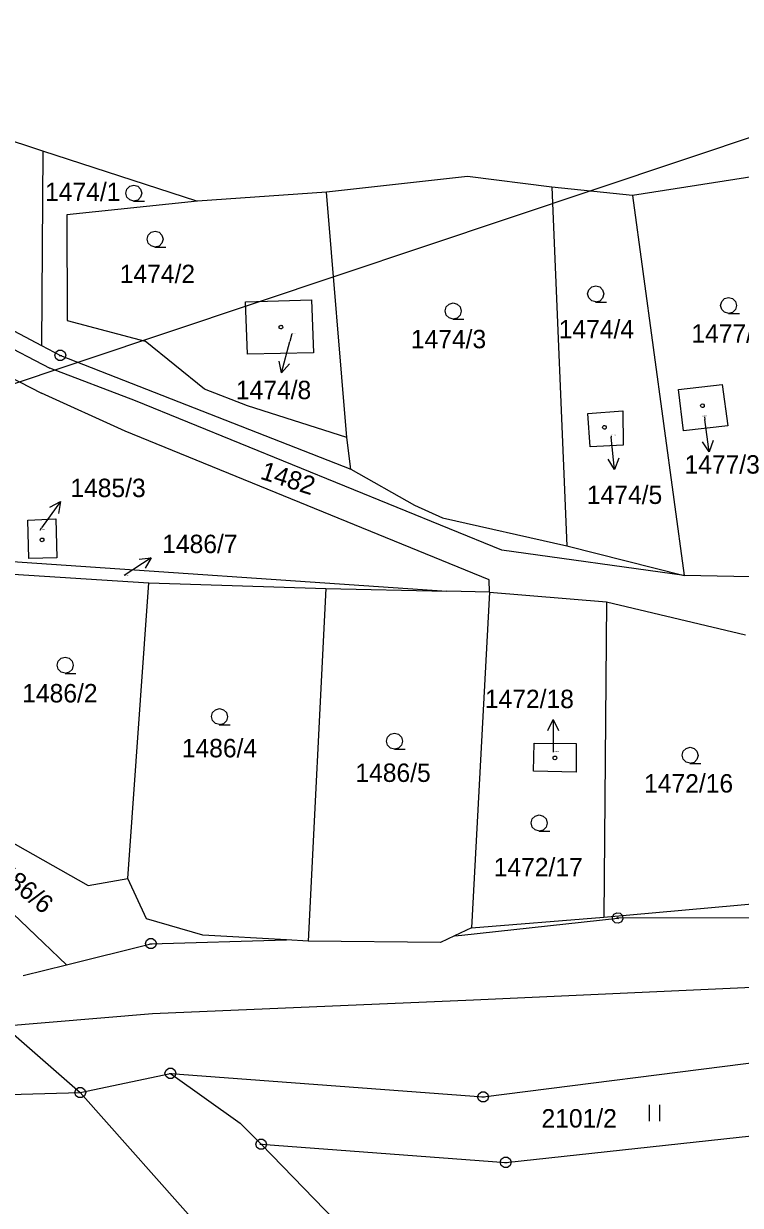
# Model space of a CAD drawing. Extents: x -806774 to -803680, y -1151731 to -1150053.
# Drawn here: x -805263 to -805196.8, y -1150678 to -1150569 of the extents above; entities that cross this region are included whole.
import ezdxf

# ---------------------------------------------------------------- set-up
doc = ezdxf.new("R2010")
doc.units = 0
for name, color, linetype in [('1', 7, 'Continuous'), ('12', 7, 'Continuous'), ('2', 7, 'Continuous'), ('3', 7, 'Continuous'), ('5', 7, 'Continuous'), ('6', 7, 'Continuous'), ('7', 7, 'Continuous'), ('8', 7, 'Continuous')]:
    doc.layers.add(name, color=color, linetype=linetype)

msp = doc.modelspace()

# ---------------------------------------------------------------- linework, layer by layer
at = {"layer": '1'}
for p, q in [((-805298.61, -1150579.03), (-805261.34, -1150598.68)), ((-805261.24, -1150580.73), (-805266.74, -1150578.94)), ((-805261.24, -1150580.73), (-805261.34, -1150598.68)), ((-805247.01, -1150585.35), (-805261.24, -1150580.73)), ((-805298.18, -1150581.32), (-805260.57, -1150600.77)), ((-805222.04, -1150583.09), (-805235.05, -1150584.53)), ((-805214.25, -1150584.07), (-805222.04, -1150583.09)), ((-805194.37, -1150582.88), (-805206.79, -1150584.83)), ((-805235.05, -1150584.53), (-805246.94, -1150585.36)), ((-805233.16, -1150607.18), (-805235.05, -1150584.53)), ((-805206.79, -1150584.83), (-805214.25, -1150584.07)), ((-805214.25, -1150584.07), (-805212.85, -1150617.17)), ((-805246.96, -1150585.36), (-805259.01, -1150586.6)), ((-805246.96, -1150585.36), (-805247.01, -1150585.35)), ((-805246.94, -1150585.36), (-805246.96, -1150585.36)), ((-805206.79, -1150584.83), (-805202.04, -1150619.89)), ((-805259.01, -1150586.6), (-805258.98, -1150596.36)), ((-805242.53, -1150594.64), (-805236.43, -1150594.46)), ((-805242.35, -1150599.49), (-805242.53, -1150594.64)), ((-805236.43, -1150594.46), (-805236.25, -1150599.34)), ((-805258.98, -1150596.36), (-805251.77, -1150598.28)), ((-805261.34, -1150598.68), (-805259.61, -1150599.59)), ((-805246.31, -1150602.71), (-805251.77, -1150598.28)), ((-805268.44, -1150599.44), (-805261.36, -1150603.09)), ((-805259.61, -1150599.59), (-805232.81, -1150610.08)), ((-805236.25, -1150599.34), (-805242.35, -1150599.49)), ((-805252.68, -1150603.77), (-805260.57, -1150600.77)), ((-805253.62, -1150606.59), (-805261.36, -1150603.09)), ((-805242.34, -1150604.24), (-805246.31, -1150602.71)), ((-805202.55, -1150602.73), (-805198.52, -1150602.28)), ((-805202.1, -1150606.56), (-805202.55, -1150602.73)), ((-805198.52, -1150602.28), (-805198.01, -1150606.08)), ((-805218.86, -1150617.58), (-805252.68, -1150603.77)), ((-805233.16, -1150607.18), (-805242.34, -1150604.24)), ((-805210.92, -1150604.95), (-805207.69, -1150604.71)), ((-805210.7, -1150608.02), (-805210.92, -1150604.95)), ((-805207.69, -1150604.71), (-805207.65, -1150607.87)), ((-805198.01, -1150606.08), (-805202.1, -1150606.56)), ((-805220.03, -1150620.31), (-805253.62, -1150606.59)), ((-805232.81, -1150610.08), (-805233.16, -1150607.18)), ((-805207.65, -1150607.87), (-805210.7, -1150608.02)), ((-805232.81, -1150610.08), (-805226.92, -1150613.4)), ((-805226.92, -1150613.4), (-805224.33, -1150614.59)), ((-805262.61, -1150614.81), (-805260.03, -1150614.67)), ((-805262.51, -1150618.33), (-805262.61, -1150614.81)), ((-805260.03, -1150614.67), (-805259.94, -1150618.26)), ((-805224.33, -1150614.59), (-805212.85, -1150617.17)), ((-805212.85, -1150617.17), (-805202.04, -1150619.89)), ((-805272.94, -1150618.01), (-805223.94, -1150621.35)), ((-805259.94, -1150618.26), (-805262.51, -1150618.33)), ((-805202.04, -1150619.89), (-805218.86, -1150617.58)), ((-805265.57, -1150619.68), (-805251.46, -1150620.59)), ((-805220.01, -1150621.44), (-805220.03, -1150620.31)), ((-805188.96, -1150620.19), (-805202.04, -1150619.89)), ((-805253.39, -1150647.87), (-805251.46, -1150620.59)), ((-805251.46, -1150620.59), (-805235.12, -1150621.11)), ((-805235.12, -1150621.11), (-805236.73, -1150653.66)), ((-805235.12, -1150621.11), (-805223.94, -1150621.35)), ((-805220.01, -1150621.44), (-805223.94, -1150621.35)), ((-805220.01, -1150621.44), (-805221.67, -1150652.43)), ((-805220.01, -1150621.44), (-805209.21, -1150622.35)), ((-805209.21, -1150622.35), (-805209.44, -1150651.45)), ((-805209.21, -1150622.35), (-805196.37, -1150625.39)), ((-805215.94, -1150637.96), (-805215.89, -1150635.38)), ((-805215.89, -1150635.38), (-805212, -1150635.4)), ((-805212, -1150635.4), (-805212, -1150638.05)), ((-805278.6, -1150637.23), (-805259.03, -1150655.84)), ((-805212, -1150638.05), (-805215.94, -1150637.96)), ((-805270.38, -1150640.96), (-805257.03, -1150648.53)), ((-805257.03, -1150648.53), (-805253.39, -1150647.87)), ((-805251.65, -1150651.59), (-805253.39, -1150647.87)), ((-805209.44, -1150651.45), (-805194.7, -1150650.11)), ((-805246.46, -1150653.1), (-805251.65, -1150651.59)), ((-805222.55, -1150653.1), (-805208.17, -1150651.53)), ((-805221.67, -1150652.43), (-805209.44, -1150651.45)), ((-805178.93, -1150651.45), (-805208.17, -1150651.53)), ((-805238.75, -1150653.54), (-805246.46, -1150653.1)), ((-805223.22, -1150653.17), (-805224.51, -1150653.79)), ((-805221.67, -1150652.43), (-805223.22, -1150653.17)), ((-805223.22, -1150653.17), (-805222.55, -1150653.1)), ((-805259.03, -1150655.84), (-805251.25, -1150653.89)), ((-805251.25, -1150653.89), (-805238.75, -1150653.54)), ((-805236.73, -1150653.66), (-805238.75, -1150653.54)), ((-805224.51, -1150653.79), (-805236.73, -1150653.66)), ((-805263.04, -1150656.84), (-805259.03, -1150655.84)), ((-805268.53, -1150658.22), (-805257.77, -1150667.64)), ((-805220.59, -1150668.04), (-805193.03, -1150664.54)), ((-805257.77, -1150667.64), (-805249.45, -1150665.86)), ((-805249.45, -1150665.86), (-805220.59, -1150668.04)), ((-805249.45, -1150665.86), (-805243, -1150670.46)), ((-805267.02, -1150667.87), (-805257.77, -1150667.64)), ((-805257.77, -1150667.64), (-805232.77, -1150695.74)), ((-805243, -1150670.46), (-805241.07, -1150672.41)), ((-805218.5, -1150674.08), (-805189.9, -1150671)), ((-805241.07, -1150672.41), (-805218.5, -1150674.08)), ((-805241.07, -1150672.41), (-805221.06, -1150693))]:
    msp.add_line(p, q, dxfattribs=at)
at = {"layer": '12'}
for p, q in [((-805242.53, -1150594.64), (-805236.43, -1150594.46)), ((-805242.35, -1150599.49), (-805242.53, -1150594.64)), ((-805236.43, -1150594.46), (-805236.25, -1150599.34)), ((-805236.25, -1150599.34), (-805242.35, -1150599.49)), ((-805202.55, -1150602.73), (-805198.52, -1150602.28)), ((-805202.1, -1150606.56), (-805202.55, -1150602.73)), ((-805198.52, -1150602.28), (-805198.01, -1150606.08)), ((-805210.92, -1150604.95), (-805207.69, -1150604.71)), ((-805210.7, -1150608.02), (-805210.92, -1150604.95)), ((-805207.69, -1150604.71), (-805207.65, -1150607.87)), ((-805198.01, -1150606.08), (-805202.1, -1150606.56)), ((-805207.65, -1150607.87), (-805210.7, -1150608.02)), ((-805262.61, -1150614.81), (-805260.03, -1150614.67)), ((-805262.51, -1150618.33), (-805262.61, -1150614.81)), ((-805260.03, -1150614.67), (-805259.94, -1150618.26)), ((-805259.94, -1150618.26), (-805262.51, -1150618.33)), ((-805215.94, -1150637.96), (-805215.89, -1150635.38)), ((-805215.89, -1150635.38), (-805212, -1150635.4)), ((-805212, -1150635.4), (-805212, -1150638.05)), ((-805212, -1150638.05), (-805215.94, -1150637.96))]:
    msp.add_line(p, q, dxfattribs=at)
at = {"layer": '3'}
for p, q in [((-805205.27, -1150668.77), (-805205.27, -1150670.27)), ((-805204.27, -1150670.27), (-805204.27, -1150668.77))]:
    msp.add_line(p, q, dxfattribs=at)
for points in [[(-805252.83, -1150585.34), (-805253.21, -1150585.24), (-805253.48, -1150584.97), (-805253.58, -1150584.6), (-805253.48, -1150584.23), (-805253.21, -1150583.96), (-805252.84, -1150583.86), (-805252.47, -1150583.96), (-805252.2, -1150584.23), (-805252.1, -1150584.61), (-805252.2, -1150584.99), (-805252.47, -1150585.26), (-805252.85, -1150585.36), (-805251.85, -1150585.36)], [(-805250.86, -1150589.59), (-805251.24, -1150589.49), (-805251.51, -1150589.22), (-805251.61, -1150588.85), (-805251.51, -1150588.48), (-805251.24, -1150588.21), (-805250.87, -1150588.11), (-805250.5, -1150588.21), (-805250.23, -1150588.48), (-805250.13, -1150588.86), (-805250.23, -1150589.24), (-805250.5, -1150589.51), (-805250.88, -1150589.61), (-805249.88, -1150589.61)], [(-805210.19, -1150594.65), (-805210.57, -1150594.55), (-805210.84, -1150594.28), (-805210.94, -1150593.91), (-805210.84, -1150593.54), (-805210.57, -1150593.27), (-805210.2, -1150593.17), (-805209.83, -1150593.27), (-805209.56, -1150593.54), (-805209.46, -1150593.92), (-805209.56, -1150594.3), (-805209.83, -1150594.57), (-805210.21, -1150594.67), (-805209.21, -1150594.67)], [(-805197.92, -1150595.71), (-805198.3, -1150595.61), (-805198.57, -1150595.34), (-805198.67, -1150594.97), (-805198.57, -1150594.6), (-805198.3, -1150594.33), (-805197.93, -1150594.23), (-805197.56, -1150594.33), (-805197.29, -1150594.6), (-805197.19, -1150594.98), (-805197.29, -1150595.36), (-805197.56, -1150595.63), (-805197.94, -1150595.73), (-805196.94, -1150595.73)], [(-805223.34, -1150596.23), (-805223.72, -1150596.13), (-805223.99, -1150595.86), (-805224.09, -1150595.49), (-805223.99, -1150595.12), (-805223.72, -1150594.85), (-805223.35, -1150594.75), (-805222.98, -1150594.85), (-805222.71, -1150595.12), (-805222.61, -1150595.5), (-805222.71, -1150595.88), (-805222.98, -1150596.15), (-805223.36, -1150596.25), (-805222.36, -1150596.25)], [(-805259.16, -1150628.92), (-805259.54, -1150628.82), (-805259.81, -1150628.55), (-805259.91, -1150628.18), (-805259.81, -1150627.81), (-805259.54, -1150627.54), (-805259.17, -1150627.44), (-805258.8, -1150627.54), (-805258.53, -1150627.81), (-805258.43, -1150628.19), (-805258.53, -1150628.57), (-805258.8, -1150628.84), (-805259.18, -1150628.94), (-805258.18, -1150628.94)], [(-805244.92, -1150633.67), (-805245.3, -1150633.57), (-805245.57, -1150633.3), (-805245.67, -1150632.93), (-805245.57, -1150632.56), (-805245.3, -1150632.29), (-805244.93, -1150632.19), (-805244.56, -1150632.29), (-805244.29, -1150632.56), (-805244.19, -1150632.94), (-805244.29, -1150633.32), (-805244.56, -1150633.59), (-805244.94, -1150633.69), (-805243.94, -1150633.69)], [(-805228.76, -1150635.93), (-805229.14, -1150635.83), (-805229.41, -1150635.56), (-805229.51, -1150635.19), (-805229.41, -1150634.82), (-805229.14, -1150634.55), (-805228.77, -1150634.45), (-805228.4, -1150634.55), (-805228.13, -1150634.82), (-805228.03, -1150635.2), (-805228.13, -1150635.58), (-805228.4, -1150635.85), (-805228.78, -1150635.95), (-805227.78, -1150635.95)], [(-805201.48, -1150637.24), (-805201.86, -1150637.14), (-805202.13, -1150636.87), (-805202.23, -1150636.5), (-805202.13, -1150636.13), (-805201.86, -1150635.86), (-805201.49, -1150635.76), (-805201.12, -1150635.86), (-805200.85, -1150636.13), (-805200.75, -1150636.51), (-805200.85, -1150636.89), (-805201.12, -1150637.16), (-805201.5, -1150637.26), (-805200.5, -1150637.26)], [(-805215.4, -1150643.49), (-805215.78, -1150643.39), (-805216.05, -1150643.12), (-805216.15, -1150642.75), (-805216.05, -1150642.38), (-805215.78, -1150642.11), (-805215.41, -1150642.01), (-805215.04, -1150642.11), (-805214.77, -1150642.38), (-805214.67, -1150642.76), (-805214.77, -1150643.14), (-805215.04, -1150643.41), (-805215.42, -1150643.51), (-805214.42, -1150643.51)]]:
    msp.add_lwpolyline(points, dxfattribs=at)
at = {"layer": '5'}
for points in [[(-805239.26, -1150596.81), (-805239.16, -1150596.83), (-805239.11, -1150596.92), (-805239.09, -1150596.98), (-805239.11, -1150597.07), (-805239.19, -1150597.14), (-805239.26, -1150597.15), (-805239.35, -1150597.12), (-805239.41, -1150597.06), (-805239.43, -1150596.98), (-805239.41, -1150596.89), (-805239.33, -1150596.82)], [(-805200.35, -1150604.07), (-805200.25, -1150604.09), (-805200.2, -1150604.18), (-805200.18, -1150604.24), (-805200.2, -1150604.33), (-805200.28, -1150604.4), (-805200.35, -1150604.41), (-805200.44, -1150604.38), (-805200.5, -1150604.32), (-805200.52, -1150604.24), (-805200.5, -1150604.15), (-805200.42, -1150604.08)], [(-805209.39, -1150606.06), (-805209.29, -1150606.08), (-805209.24, -1150606.17), (-805209.22, -1150606.23), (-805209.24, -1150606.32), (-805209.32, -1150606.39), (-805209.39, -1150606.4), (-805209.48, -1150606.37), (-805209.54, -1150606.31), (-805209.56, -1150606.23), (-805209.54, -1150606.14), (-805209.46, -1150606.07)], [(-805261.3, -1150616.45), (-805261.2, -1150616.47), (-805261.15, -1150616.56), (-805261.13, -1150616.62), (-805261.15, -1150616.71), (-805261.23, -1150616.78), (-805261.3, -1150616.79), (-805261.39, -1150616.76), (-805261.45, -1150616.7), (-805261.47, -1150616.62), (-805261.45, -1150616.53), (-805261.37, -1150616.46)], [(-805213.96, -1150636.57), (-805213.86, -1150636.59), (-805213.81, -1150636.68), (-805213.79, -1150636.74), (-805213.81, -1150636.83), (-805213.89, -1150636.9), (-805213.96, -1150636.91), (-805214.05, -1150636.88), (-805214.11, -1150636.82), (-805214.13, -1150636.74), (-805214.11, -1150636.65), (-805214.03, -1150636.58)]]:
    msp.add_lwpolyline(points, close=True, dxfattribs=at)
at = {"layer": '6'}
for p, q in [((-805267.37, -1150603.37), (-805132.32, -1150558.17)), ((-805221.49, -1150659.08), (-805193.46, -1150657.79)), ((-805251.1, -1150660.35), (-805221.49, -1150659.08)), ((-805269.95, -1150661.91), (-805251.1, -1150660.35))]:
    msp.add_line(p, q, dxfattribs=at)
at = {"layer": '7'}
for p, q in [((-805238.25, -1150597.61), (-805238.43, -1150598.3)), ((-805239.2, -1150601.2), (-805238.43, -1150598.3)), ((-805200.15, -1150605.26), (-805200.11, -1150605.51)), ((-805199.73, -1150608.49), (-805200.11, -1150605.51)), ((-805208.78, -1150607), (-805208.77, -1150607.14)), ((-805208.45, -1150610.12), (-805208.77, -1150607.14)), ((-805259.59, -1150613.08), (-805261.34, -1150615.52)), ((-805261.48, -1150615.71), (-805261.34, -1150615.52)), ((-805251.22, -1150618.26), (-805253.72, -1150619.92)), ((-805214.13, -1150633.21), (-805214.13, -1150636.21))]:
    msp.add_line(p, q, dxfattribs=at)
for points in [[(-805238.46, -1150600.36), (-805239.2, -1150601.2), (-805239.42, -1150600.11)], [(-805199.36, -1150607.43), (-805199.73, -1150608.49), (-805200.35, -1150607.56)], [(-805208.06, -1150609.08), (-805208.45, -1150610.12), (-805209.06, -1150609.18)], [(-805260.58, -1150613.6), (-805259.59, -1150613.08), (-805259.77, -1150614.19)], [(-805252.33, -1150618.4), (-805251.22, -1150618.26), (-805251.78, -1150619.23)], [(-805214.63, -1150634.21), (-805214.13, -1150633.21), (-805213.63, -1150634.21)]]:
    msp.add_lwpolyline(points, dxfattribs=at)
at = {"layer": '8'}
for p, q in [((-805259.73, -1150599.59), (-805259.49, -1150599.59)), ((-805208.25, -1150651.45), (-805208.09, -1150651.61)), ((-805251.37, -1150653.89), (-805251.13, -1150653.89)), ((-805249.57, -1150665.86), (-805249.33, -1150665.86)), ((-805257.89, -1150667.64), (-805257.65, -1150667.64)), ((-805220.71, -1150668.04), (-805220.47, -1150668.04)), ((-805241.19, -1150672.41), (-805240.95, -1150672.41)), ((-805218.62, -1150674.08), (-805218.38, -1150674.08))]:
    msp.add_line(p, q, dxfattribs=at)
for points in [[(-805259.46, -1150599.11), (-805259.21, -1150599.29), (-805259.11, -1150599.58), (-805259.21, -1150599.87), (-805259.46, -1150600.05), (-805259.77, -1150600.05), (-805260.02, -1150599.87), (-805260.12, -1150599.58), (-805260.02, -1150599.29), (-805259.77, -1150599.11)], [(-805207.72, -1150651.3), (-805207.68, -1150651.6), (-805207.81, -1150651.88), (-805208.09, -1150652.01), (-805208.39, -1150651.96), (-805208.61, -1150651.74), (-805208.66, -1150651.44), (-805208.52, -1150651.16), (-805208.25, -1150651.03), (-805207.94, -1150651.08)], [(-805251.1, -1150653.41), (-805250.85, -1150653.59), (-805250.75, -1150653.88), (-805250.85, -1150654.17), (-805251.1, -1150654.35), (-805251.41, -1150654.35), (-805251.66, -1150654.17), (-805251.76, -1150653.88), (-805251.66, -1150653.59), (-805251.41, -1150653.41)], [(-805249.3, -1150665.38), (-805249.05, -1150665.56), (-805248.95, -1150665.85), (-805249.05, -1150666.14), (-805249.3, -1150666.32), (-805249.61, -1150666.32), (-805249.86, -1150666.14), (-805249.96, -1150665.85), (-805249.86, -1150665.56), (-805249.61, -1150665.38)], [(-805257.62, -1150667.16), (-805257.37, -1150667.34), (-805257.27, -1150667.63), (-805257.37, -1150667.92), (-805257.62, -1150668.1), (-805257.93, -1150668.1), (-805258.18, -1150667.92), (-805258.28, -1150667.63), (-805258.18, -1150667.34), (-805257.93, -1150667.16)], [(-805220.44, -1150667.56), (-805220.19, -1150667.74), (-805220.09, -1150668.03), (-805220.19, -1150668.32), (-805220.44, -1150668.5), (-805220.75, -1150668.5), (-805221, -1150668.32), (-805221.1, -1150668.03), (-805221, -1150667.74), (-805220.75, -1150667.56)], [(-805240.92, -1150671.93), (-805240.67, -1150672.11), (-805240.57, -1150672.4), (-805240.67, -1150672.69), (-805240.92, -1150672.87), (-805241.23, -1150672.87), (-805241.48, -1150672.69), (-805241.58, -1150672.4), (-805241.48, -1150672.11), (-805241.23, -1150671.93)], [(-805218.35, -1150673.6), (-805218.1, -1150673.78), (-805218, -1150674.07), (-805218.1, -1150674.36), (-805218.35, -1150674.54), (-805218.66, -1150674.54), (-805218.91, -1150674.36), (-805219.01, -1150674.07), (-805218.91, -1150673.78), (-805218.66, -1150673.6)]]:
    msp.add_lwpolyline(points, close=True, dxfattribs=at)

# ---------------------------------------------------------------- texts
at = {"layer": '2'}
for s, height, p in [('1474/1', 1.7, (-805261.02, -1150585.34)), ('1474/2', 1.7, (-805254.13, -1150592.92)), ('1474/4', 1.7, (-805213.61, -1150598.02)), ('1474/8', 0.1, (-805238.23, -1150597.61)), ('1474/3', 1.7, (-805227.26, -1150598.93)), ('1477/1', 1.7, (-805201.37, -1150598.41)), ('1477/3', 0.1, (-805200.37, -1150605.26)), ('1474/5', 0.1, (-805208.76, -1150607)), ('1485/3', 0.1, (-805261.46, -1150615.71)), ('1486/7', 0.1, (-805253.7, -1150619.92)), ('1486/2', 1.7, (-805263.13, -1150631.62)), ('1486/4', 1.7, (-805248.4, -1150636.69)), ('1472/18', 0.1, (-805214.11, -1150636.21)), ('1486/5', 1.7, (-805232.38, -1150638.96)), ('1472/16', 1.7, (-805205.73, -1150639.94)), ('1472/17', 1.7, (-805219.61, -1150647.67)), ('2101/2', 1.7, (-805215.2, -1150670.86))]:
    msp.add_text(s, height=height, dxfattribs=at).set_placement(p)
for s, rotation, p in [('1482', 341.9985, (-805241.25, -1150610.95)), ('1486/6', 320.5699, (-805266.53, -1150646.81))]:
    msp.add_text(s, height=1.7, rotation=rotation, dxfattribs=at).set_placement(p)
at = {"layer": '7'}
for s, p in [('1474/8', (-805243.41, -1150603.63)), ('1477/3', (-805202, -1150610.5)), ('1485/3', (-805258.69, -1150612.67)), ('1474/5', (-805211.01, -1150613.3)), ('1486/7', (-805250.21, -1150617.84)), ('1472/18', (-805220.43, -1150632.15))]:
    msp.add_text(s, height=1.7, dxfattribs=at).set_placement(p)

doc.saveas('drawing.dxf')
